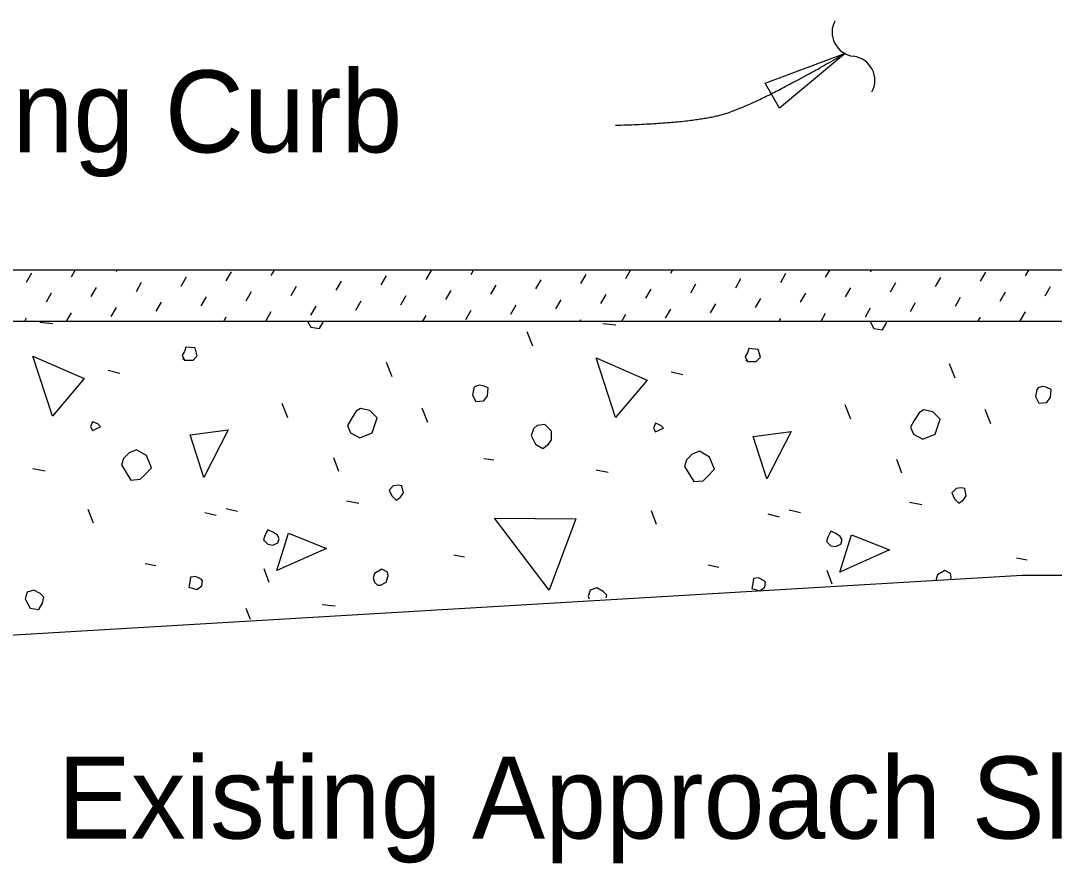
# Model space of a CAD drawing. Extents: x 21587 to 21659.1, y 56116.2 to 56157.3.
# Drawn here: x 21596.717 to 21599.259, y 56132.593 to 56134.664 of the extents above; entities that cross this region are included whole.
import ezdxf

# ---------------------------------------------------------------- set-up
doc = ezdxf.new("R2010")
doc.units = 0
for name, color, linetype in [('AdhocPoint_dp', 7, 'Continuous'), ('PlotBorder_dp', 7, 'Continuous'), ('SheetBorder_dp', 7, 'Continuous'), ('TextMisc', 7, 'Continuous')]:
    doc.layers.add(name, color=color, linetype=linetype)

msp = doc.modelspace()

# ---------------------------------------------------------------- linework, layer by layer
at = {"layer": 'AdhocPoint_dp'}
for p, q in [((21604.323, 56134.0511), (21593.9596, 56134.0511)), ((21593.9596, 56133.926), (21604.323, 56133.926)), ((21599.1795, 56133.301), (21594.9595, 56133.051)), ((21604.323, 56133.301), (21599.1795, 56133.301))]:
    msp.add_line(p, q, dxfattribs=at)
at = {"layer": 'PlotBorder_dp'}
msp.add_lwpolyline([(21598.7452, 56134.5845), (21598.5825, 56134.4497), (21598.5472, 56134.5108)], close=True, dxfattribs=at)
for centre, start, end in [((21598.7718, 56134.636), 151.5267, 263.2539), ((21598.7578, 56134.5176), 331.5267, 83.2539)]:
    msp.add_arc(centre, 0.0596, start, end, dxfattribs=at)
msp.add_open_spline([(21598.1795, 56134.4075), (21598.3612, 56134.4122), (21598.5204, 56134.4546), (21598.7452, 56134.5845)], degree=2, dxfattribs=at)
at = {"layer": 'TextMisc'}
for p, q in [((21596.7309, 56134.0219), (21596.7438, 56134.0443)), ((21596.8415, 56134.0349), (21596.8509, 56134.0511)), ((21596.9521, 56134.0479), (21596.954, 56134.0511)), ((21597.2222, 56134.0249), (21597.2352, 56134.0473)), ((21597.3329, 56134.0379), (21597.3405, 56134.0511)), ((21597.4435, 56134.0509), (21597.4436, 56134.0511)), ((21597.7136, 56134.028), (21597.7266, 56134.0504)), ((21597.8242, 56134.0409), (21597.8301, 56134.0511)), ((21598.0943, 56134.018), (21598.1073, 56134.0404)), ((21598.205, 56134.031), (21598.2166, 56134.0511)), ((21598.3156, 56134.044), (21598.3197, 56134.0511)), ((21598.5857, 56134.021), (21598.5987, 56134.0434)), ((21598.6963, 56134.034), (21598.7062, 56134.0511)), ((21598.807, 56134.047), (21598.8094, 56134.0511)), ((21599.0771, 56134.0241), (21599.09, 56134.0465)), ((21599.1877, 56134.037), (21599.1958, 56134.0511)), ((21597.001, 56133.999), (21597.0139, 56134.0214)), ((21597.1116, 56134.012), (21597.1246, 56134.0344)), ((21597.4923, 56134.002), (21597.5053, 56134.0244)), ((21597.603, 56134.015), (21597.6159, 56134.0374)), ((21597.8731, 56133.9921), (21597.886, 56134.0145)), ((21597.9837, 56134.0051), (21597.9967, 56134.0275)), ((21598.3644, 56133.9951), (21598.3774, 56134.0175)), ((21598.4751, 56134.0081), (21598.488, 56134.0305)), ((21598.8558, 56133.9981), (21598.8688, 56134.0205)), ((21598.9664, 56134.0111), (21598.9794, 56134.0335)), ((21596.7797, 56133.9731), (21596.7927, 56133.9955)), ((21596.8903, 56133.9861), (21596.9033, 56134.0084)), ((21597.2711, 56133.9761), (21597.284, 56133.9985)), ((21597.3817, 56133.9891), (21597.3947, 56134.0115)), ((21597.6518, 56133.9662), (21597.6648, 56133.9886)), ((21597.7624, 56133.9791), (21597.7754, 56134.0015)), ((21598.1432, 56133.9692), (21598.1561, 56133.9916)), ((21598.2538, 56133.9822), (21598.2668, 56134.0045)), ((21598.6345, 56133.9722), (21598.6475, 56133.9946)), ((21598.7452, 56133.9852), (21598.7581, 56134.0076)), ((21599.1259, 56133.9752), (21599.1389, 56133.9976)), ((21599.2365, 56133.9882), (21599.2495, 56134.0106)), ((21597.0498, 56133.9502), (21597.0628, 56133.9726)), ((21597.1604, 56133.9631), (21597.1734, 56133.9855)), ((21597.4305, 56133.9402), (21597.4435, 56133.9626)), ((21597.5412, 56133.9532), (21597.5541, 56133.9756)), ((21597.9219, 56133.9433), (21597.9349, 56133.9657)), ((21598.0325, 56133.9562), (21598.0455, 56133.9786)), ((21598.4133, 56133.9463), (21598.4262, 56133.9687)), ((21598.5239, 56133.9592), (21598.5369, 56133.9816)), ((21598.9046, 56133.9493), (21598.9176, 56133.9717)), ((21599.0153, 56133.9623), (21599.0282, 56133.9847)), ((21596.8296, 56133.926), (21596.8415, 56133.9466)), ((21596.9392, 56133.9372), (21596.9521, 56133.9596)), ((21597.2161, 56133.926), (21597.2222, 56133.9367)), ((21597.3199, 56133.9273), (21597.3329, 56133.9497)), ((21597.7057, 56133.926), (21597.7136, 56133.9397)), ((21597.8113, 56133.9303), (21597.8242, 56133.9527)), ((21598.1953, 56133.926), (21598.205, 56133.9427)), ((21598.3026, 56133.9333), (21598.3156, 56133.9557)), ((21598.6849, 56133.926), (21598.6963, 56133.9458)), ((21598.794, 56133.9363), (21598.807, 56133.9587)), ((21599.1747, 56133.9264), (21599.1877, 56133.9488)), ((21596.7264, 56133.926), (21596.7309, 56133.9337)), ((21596.7639, 56133.9236), (21596.7957, 56133.9201)), ((21597.6025, 56133.926), (21597.603, 56133.9268)), ((21598.0922, 56133.926), (21598.0943, 56133.9298)), ((21598.1485, 56133.9201), (21598.1804, 56133.9165)), ((21598.5818, 56133.926), (21598.5857, 56133.9328)), ((21599.0714, 56133.926), (21599.0771, 56133.9358)), ((21597.9759, 56133.8641), (21597.9618, 56133.8995)), ((21597.6301, 56133.7892), (21597.6159, 56133.8246)), ((21599.0148, 56133.7857), (21599.0006, 56133.8211)), ((21596.9318, 56133.8051), (21596.9601, 56133.7981)), ((21598.3165, 56133.8016), (21598.3448, 56133.7945)), ((21597.3737, 56133.6885), (21597.3596, 56133.7238)), ((21597.7178, 56133.6767), (21597.7037, 56133.7121)), ((21598.7584, 56133.6849), (21598.7443, 56133.7203)), ((21599.1025, 56133.6732), (21599.0884, 56133.7085)), ((21597.4993, 56133.5559), (21597.4869, 56133.5895)), ((21597.8557, 56133.5883), (21597.8805, 56133.5848)), ((21598.8839, 56133.5524), (21598.8716, 56133.5859)), ((21596.7468, 56133.5636), (21596.7769, 56133.5583)), ((21598.1315, 56133.5601), (21598.1615, 56133.5547)), ((21597.5181, 56133.484), (21597.5481, 56133.4787)), ((21598.9028, 56133.4805), (21598.9328, 56133.4752)), ((21596.8953, 56133.4292), (21596.8829, 56133.4628)), ((21597.1693, 56133.4558), (21597.1976, 56133.4487)), ((21597.2217, 56133.4657), (21597.25, 56133.4587)), ((21598.28, 56133.4257), (21598.2676, 56133.4593)), ((21598.6064, 56133.4622), (21598.6347, 56133.4551)), ((21598.554, 56133.4522), (21598.5823, 56133.4451)), ((21597.7815, 56133.3515), (21597.808, 56133.3462)), ((21597.0226, 56133.3302), (21597.0491, 56133.3249)), ((21598.4073, 56133.3267), (21598.4338, 56133.3214)), ((21599.1657, 56133.3444), (21599.1922, 56133.3391)), ((21597.3278, 56133.2831), (21597.3154, 56133.3167)), ((21598.7125, 56133.2796), (21598.7001, 56133.3132)), ((21597.458, 56133.2295), (21597.4898, 56133.2259)), ((21597.2818, 56133.1928), (21597.2712, 56133.2194))]:
    msp.add_line(p, q, dxfattribs=at)
for points in [[(21597.4221, 56133.926), (21597.4303, 56133.9112), (21597.4515, 56133.9077), (21597.4604, 56133.9236), (21597.461, 56133.926)], [(21598.8049, 56133.926), (21598.8062, 56133.9236)], [(21598.8062, 56133.9236), (21598.815, 56133.9077), (21598.8362, 56133.9041), (21598.845, 56133.9201), (21598.8465, 56133.926)], [(21597.1192, 56133.8299), (21597.1404, 56133.8299), (21597.151, 56133.8405), (21597.1457, 56133.8599), (21597.1227, 56133.8617), (21597.1192, 56133.8511), (21597.1139, 56133.8423), (21597.1192, 56133.8299), (21597.1157, 56133.8334)], [(21596.7945, 56133.6926), (21596.7468, 56133.8394), (21596.8723, 56133.7846), (21596.7945, 56133.6926)], [(21598.1792, 56133.6891), (21598.1315, 56133.8358), (21598.257, 56133.781), (21598.1792, 56133.6891)], [(21598.5039, 56133.8264), (21598.5251, 56133.8264), (21598.5357, 56133.837), (21598.5304, 56133.8564), (21598.5074, 56133.8582), (21598.5039, 56133.8476), (21598.4986, 56133.8387), (21598.5039, 56133.8264), (21598.5003, 56133.8299)], [(21597.8274, 56133.7439), (21597.8363, 56133.728), (21597.8557, 56133.7298), (21597.8646, 56133.7421), (21597.8663, 56133.7616), (21597.854, 56133.7669), (21597.8451, 56133.7686), (21597.8345, 56133.7651), (21597.831, 56133.7616), (21597.8274, 56133.7439)], [(21599.2121, 56133.7404), (21599.221, 56133.7245), (21599.2404, 56133.7262), (21599.2492, 56133.7386), (21599.251, 56133.758), (21599.2386, 56133.7633), (21599.2298, 56133.7651), (21599.2192, 56133.7616), (21599.2156, 56133.758), (21599.2121, 56133.7404)], [(21597.5275, 56133.6514), (21597.5505, 56133.639), (21597.5806, 56133.6514), (21597.593, 56133.6885), (21597.5753, 56133.7062), (21597.5523, 56133.7115), (21597.5417, 56133.7044), (21597.5293, 56133.6849), (21597.5205, 56133.669), (21597.5275, 56133.6514)], [(21598.9122, 56133.6478), (21598.9352, 56133.6354), (21598.9653, 56133.6478), (21598.9776, 56133.6849), (21598.9599, 56133.7026), (21598.937, 56133.7079), (21598.9264, 56133.7008), (21598.914, 56133.6814), (21598.9051, 56133.6655), (21598.9122, 56133.6478)], [(21596.8935, 56133.6573), (21596.913, 56133.6661), (21596.9059, 56133.6732), (21596.8935, 56133.6785), (21596.8882, 56133.6661), (21596.8935, 56133.6573)], [(21597.1669, 56133.5417), (21597.1333, 56133.646), (21597.227, 56133.6584), (21597.1669, 56133.5417)], [(21597.9724, 56133.6449), (21597.983, 56133.6237), (21598.0007, 56133.6131), (21598.0148, 56133.6237), (21598.0219, 56133.6343), (21598.0219, 56133.6555), (21598.006, 56133.6714), (21597.9865, 56133.6697), (21597.9777, 56133.6608), (21597.9724, 56133.6449)], [(21598.2782, 56133.6537), (21598.2977, 56133.6626), (21598.2906, 56133.6697), (21598.2782, 56133.675), (21598.2729, 56133.6626), (21598.2782, 56133.6537)], [(21598.5516, 56133.5382), (21598.518, 56133.6425), (21598.6117, 56133.6549), (21598.5516, 56133.5382)], [(21596.9643, 56133.5724), (21596.9872, 56133.5353), (21597.0102, 56133.5371), (21597.0191, 56133.5459), (21597.0385, 56133.5654), (21597.0261, 56133.5954), (21597.0014, 56133.6096), (21596.9837, 56133.6025), (21596.9696, 56133.5883), (21596.9643, 56133.5724)], [(21598.3489, 56133.5689), (21598.3719, 56133.5318), (21598.3949, 56133.5335), (21598.4037, 56133.5424), (21598.4232, 56133.5618), (21598.4108, 56133.5919), (21598.3861, 56133.606), (21598.3684, 56133.5989), (21598.3542, 56133.5848), (21598.3489, 56133.5689)], [(21597.6294, 56133.4964), (21597.6401, 56133.4858), (21597.6507, 56133.4929), (21597.6577, 56133.5035), (21597.6542, 56133.5212), (21597.6454, 56133.5229), (21597.633, 56133.5212), (21597.6224, 56133.5106), (21597.6294, 56133.4964)], [(21599.0136, 56133.4893), (21599.0242, 56133.4787), (21599.0348, 56133.4858), (21599.0419, 56133.4964), (21599.0384, 56133.5141), (21599.0295, 56133.5159), (21599.0172, 56133.5141), (21599.0066, 56133.5035), (21599.0136, 56133.4893)], [(21598.0166, 56133.2648), (21597.8822, 56133.4416), (21598.082, 56133.4398), (21598.0166, 56133.2648)], [(21597.3242, 56133.3773), (21597.3366, 56133.3756), (21597.349, 56133.3809), (21597.3525, 56133.3915), (21597.3472, 56133.4003), (21597.3366, 56133.4074), (21597.3242, 56133.4127), (21597.3172, 56133.3986), (21597.3136, 56133.388), (21597.3242, 56133.3773)], [(21597.3466, 56133.3126), (21597.3749, 56133.4045), (21597.4686, 56133.3674), (21597.3466, 56133.3126)], [(21598.7089, 56133.3738), (21598.7213, 56133.372), (21598.7337, 56133.3773), (21598.7372, 56133.388), (21598.7319, 56133.3968), (21598.7213, 56133.4039), (21598.7089, 56133.4092), (21598.7019, 56133.395), (21598.6983, 56133.3844), (21598.7089, 56133.3738)], [(21598.7313, 56133.309), (21598.7596, 56133.401), (21598.8533, 56133.3638), (21598.7313, 56133.309)], [(21597.5941, 56133.2772), (21597.6012, 56133.2772), (21597.6153, 56133.2843), (21597.6206, 56133.3002), (21597.6188, 56133.309), (21597.6047, 56133.3161), (21597.587, 56133.3055), (21597.5835, 56133.2949), (21597.587, 56133.2843), (21597.5941, 56133.2772)], [(21599.003, 56133.2899), (21599.0053, 56133.2967), (21599.0035, 56133.3055), (21598.9894, 56133.3126), (21598.9717, 56133.302), (21598.9682, 56133.2914), (21598.9693, 56133.2878)], [(21597.1304, 56133.2719), (21597.1499, 56133.2666), (21597.1622, 56133.2754), (21597.164, 56133.2878), (21597.1605, 56133.2914), (21597.1463, 56133.2984), (21597.134, 56133.2967), (21597.1322, 56133.2843), (21597.1304, 56133.2719)], [(21598.5151, 56133.2684), (21598.5345, 56133.2631), (21598.5469, 56133.2719), (21598.5487, 56133.2843), (21598.5452, 56133.2878), (21598.531, 56133.2949), (21598.5186, 56133.2931), (21598.5169, 56133.2807), (21598.5151, 56133.2684)], [(21596.7309, 56133.2366), (21596.7397, 56133.2206), (21596.761, 56133.2171), (21596.7698, 56133.233), (21596.7733, 56133.2472), (21596.7645, 56133.256), (21596.7486, 56133.2648), (21596.7327, 56133.2595), (21596.7274, 56133.2436), (21596.7309, 56133.2366)], [(21598.1564, 56133.2458), (21598.158, 56133.2524), (21598.1492, 56133.2612), (21598.1333, 56133.2701), (21598.1174, 56133.2648), (21598.112, 56133.2489), (21598.1149, 56133.2432)]]:
    msp.add_lwpolyline(points, dxfattribs=at)

# ---------------------------------------------------------------- texts
at = {"layer": 'SheetBorder_dp'}
for s, p in [('Existing Curb', (21596.0521, 56134.3406)), ('Existing Approach Slab', (21596.8077, 56132.654))]:
    msp.add_text(s, height=0.2016, dxfattribs=at).set_placement(p)

doc.saveas('drawing.dxf')
